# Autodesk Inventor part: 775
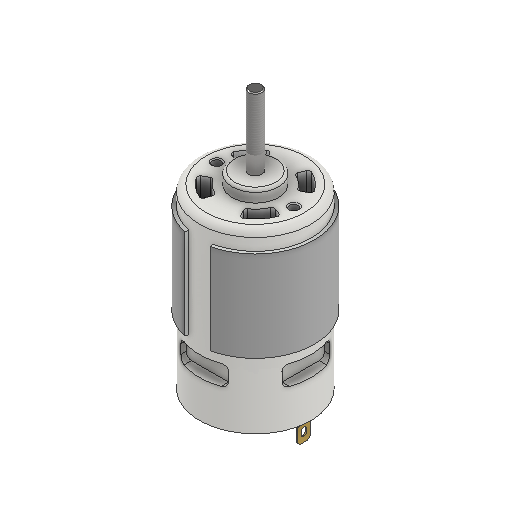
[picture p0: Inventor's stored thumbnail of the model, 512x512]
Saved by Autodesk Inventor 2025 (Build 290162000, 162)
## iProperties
Created: 2024-09
Part Number: 775
Material: Generico
Document SubType Name: Modeling
Designer: R5800u
Density: 1 g/cm^3
Appearance: Default
Author: R5800u
Revision Number: ANY
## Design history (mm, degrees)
feature "Aufsatz-Linear austragen3"
feature "Schnitt-Linear austragen7"
feature "Aufsatz-Linear austragen7[1]"
feature "Aufsatz-Linear austragen7[2]"
feature "Aufsatz-Linear austragen8"
feature "Aufsatz-Linear austragen9"
feature "Aufsatz-Linear austragen10[1]"
feature "Aufsatz-Linear austragen10[2]"
feature "Aufsatz-Linear austragen10[3]"
feature "Aufsatz-Linear austragen10[5]"
feature "Aufsatz-Linear austragen10[6]"
feature "Aufsatz-Linear austragen10[7]"
feature "Aufsatz-Linear austragen10[8]"
feature "Schnitt-Linear austragen8"
sketch "Schizzo1"
  geometry: C1 r 1.5 at (0, 0) reference; C2 r 2.5 at (0, 0); 1 further point
  constraints: 1 centre point, 1 coincident
  dimensions: "d0" = 5 diameter of C2
extrude "Estrusione1" join sketch "Schizzo1" distance "d1" = 27; taper "d2" = 0 deg
sketch "Schizzo2"
  geometry: L1 (-2, -1.5)-(-2, 1.5); A1 r 2.5 centre (0, 0) between (-2, -1.5) and (-2, 1.5) reference; 1 further point
  constraints: 2 end point, 2 point on circle, 1 vertical
  dimensions: "d3" = 2 distance from line of point (0, 0) L1
extrude "Estrusione2" cut sketch "Schizzo2" distance "d4" = 22; taper "d5" = 0 deg
chamfer "Smusso1" distance "d6" = 0.4; stored, may be unused: second distance "d7" = 2, angle "d8" = 45 deg
sketch "Schizzo3"
  geometry: L1 (0, 0)-(0, -25.175); C1 r 1.5 at (0, 0) reference; 3 further points
  constraints: 2 end point, 1 symmetric about line, 1 vertical
  dimensions: "d9" = 14.5 distance from line of L1 point (14.5, 0)
hole "Foro1" sketch "Schizzo3" at (14.5, 0), (-14.5, 0) diameter "d10" = 3.242; stored, may be unused: countersink angle "d14" = 89.9544 deg, drill point angle "d16" = 118 deg; dims "d11" = 8, "d12" = 8, "d13" = 4.6, "d15" = 11.8
chamfer "Smusso2" distance "d17" = 0.4; stored, may be unused: second distance "d18" = 2, angle "d19" = 45 deg
feature "Filettatura1" dims "d20" = 20, "d21" = 0
sketch "Schizzo4"
  geometry: L1 (0, 0)-(5.472, 15.035); L2 (0, 0)-(16, 0); L3 (-0.092, 0.52)-(-0.092, 23.069); L4 (0, 0)-(13.856, 8); L5 (0, 0)-(16, 0); C1 r 2.5 at (0, 0) reference; C2 r 11.5 at (0, 0); A1 r 16 centre (0, 0) between (5.472, 15.035) and (13.856, 8); 3 further points
  constraints: 10 end point, 2 centre point, 2 coincident, 2 equal length, 2 horizontal, 2 point on circle, 1 vertical
  dimensions: "d22" = 23 diameter of C2; "d23" = 32 diameter of A1; "d24" = 70 deg angle of L2 L1; "d25" = 30 deg angle of L5 L4
extrude "Estrusione3" cut sketch "Schizzo4" distance "d26" = 10; taper "d27" = 0 deg
fillet "Raccordo1" dims "d31" = 1
pattern_circular "Serie circolare2" dims "d33" = 360 deg
node "Solido1"
node "Solido2"
node "Solido3"
node "Solido4"
node "Solido5"
node "Solido6"
node "Solido7"
node "Solido8"
node "Solido9"
node "Solido10"
node "Solido11"
node "Solido12"
node "Solido13"
node "Solido14"
